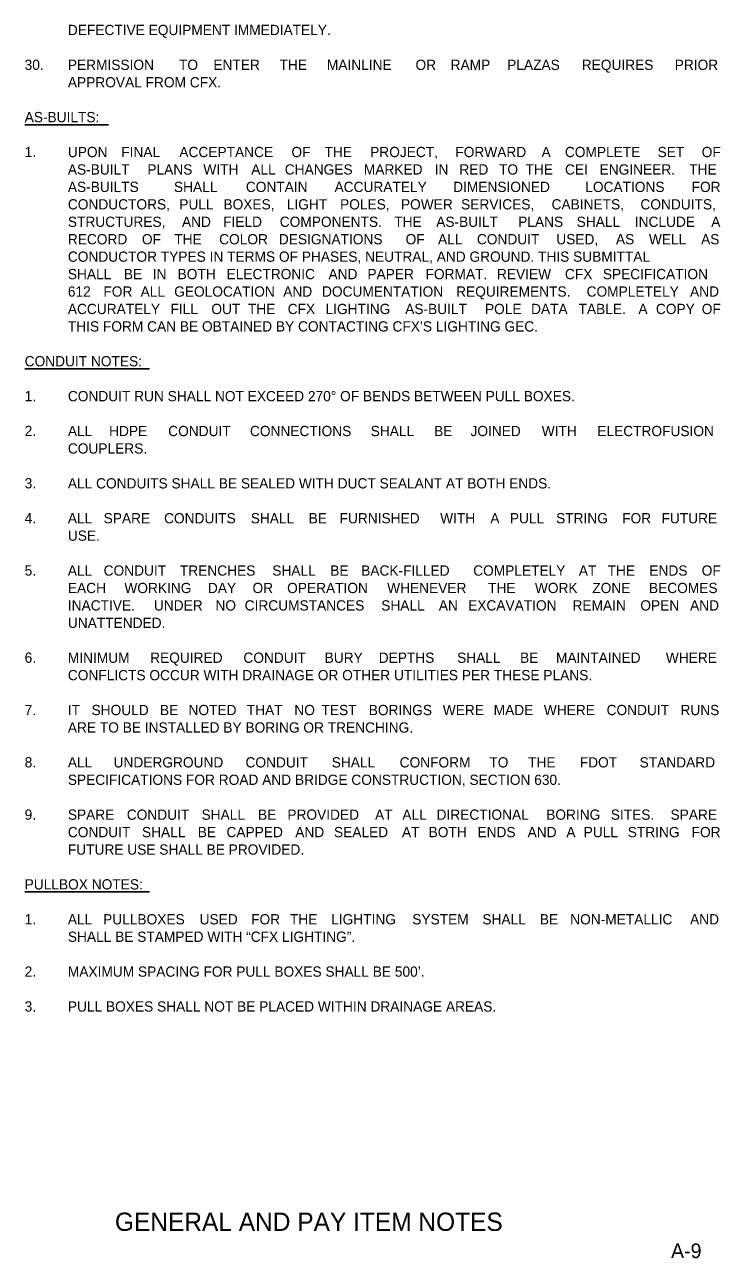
# Model space of a CAD drawing. Extents: x -55 to 2471539, y -90 to 3608906.
# Drawn here: x 1052 to 1526, y -65 to 777 of the extents above; entities that cross this region are included whole.
import ezdxf

# ---------------------------------------------------------------- set-up
doc = ezdxf.new("R2010")
doc.units = 0
for name, color, linetype in [('SheetLines_dp', 7, 'Continuous'), ('TextMisc', 7, 'Continuous'), ('XSCell', 7, 'Continuous')]:
    doc.layers.add(name, color=color, linetype=linetype)

msp = doc.modelspace()

# ---------------------------------------------------------------- linework, layer by layer
at = {"layer": 'XSCell'}
for p, q in [((1051.51, 708.96), (1108.73, 708.96)), ((1051.51, 542.36), (1136.69, 542.36)), ((1051.51, 185.36), (1136.73, 185.36))]:
    msp.add_line(p, q, dxfattribs=at)

# ---------------------------------------------------------------- texts
at = {"layer": 'SheetLines_dp'}
msp.add_text('A-9', height=10, dxfattribs=at).set_placement((1492.64, -64.49))
at = {"layer": 'TextMisc'}
msp.add_text('GENERAL AND PAY ITEM NOTES ', height=12.5, dxfattribs=at).set_placement((1113.09, -45.92))
at = {"layer": 'XSCell'}
for s, p in [('DEFECTIVE EQUIPMENT IMMEDIATELY.', (1080.99, 770.14)), ('30.', (1051.5, 746.38)), ('PERMISSION ', (1080.99, 746.34)), ('TO ', (1156.84, 746.34)), ('ENTER ', (1180.3, 746.34)), ('THE ', (1225.48, 746.34)), ('MAINLINE ', (1257.78, 746.34)), ('OR ', (1318.26, 746.34)), ('RAMP ', (1342.22, 746.34)), ('PLAZAS ', (1380.82, 746.34)), ('REQUIRES ', (1431.73, 746.34)), ('PRIOR ', (1495.16, 746.34)), ('APPROVAL FROM CFX.', (1080.99, 734.44)), ('AS-BUILTS:', (1051.5, 710.68)), ('1.', (1051.5, 686.88)), ('UPON ', (1080.99, 686.84)), ('FINAL ', (1117.41, 686.84)), ('ACCEPTANCE ', (1157.09, 686.84)), ('OF ', (1233.58, 686.84)), ('THE ', (1256.2, 686.84)), ('PROJECT, ', (1287.31, 686.84)), ('FORWARD ', (1345.45, 686.84)), ('A ', (1404.28, 686.84)), ('COMPLETE ', (1420.22, 686.84)), ('SET ', (1483.47, 686.84)), ('OF ', (1513.59, 686.84)), ('AS-BUILT ', (1080.99, 674.94)), ('PLANS ', (1135.26, 674.94)), ('WITH ', (1173.46, 674.94)), ('ALL ', (1206.16, 674.94)), ('CHANGES ', (1229.03, 674.94)), ('MARKED ', (1283, 674.94)), ('IN ', (1331.35, 674.94)), ('RED ', (1348.18, 674.94)), ('TO ', (1375.25, 674.94)), ('THE ', (1393.35, 674.94)), ('CEI ', (1420.3, 674.94)), ('ENGINEER. ', (1443.89, 674.94)), ('THE ', (1505.1, 674.94)), ('AS-BUILTS ', (1080.99, 663.04)), ('SHALL ', (1153.39, 663.04)), ('CONTAIN ', (1202.46, 663.04)), ('ACCURATELY ', (1263, 663.04)), ('DIMENSIONED ', (1343.94, 663.04)), ('LOCATIONS ', (1434.11, 663.04)), ('FOR ', (1506.71, 663.04)), ('CONDUCTORS, ', (1080.99, 651.14)), ('PULL ', (1157.04, 651.14)), ('BOXES, ', (1187.18, 651.14)), ('LIGHT ', (1230.39, 651.14)), ('POLES, ', (1266.78, 651.14)), ('POWER ', (1308.31, 651.14)), ('SERVICES, ', (1349.37, 651.14)), ('CABINETS, ', (1411.13, 651.14)), ('CONDUITS, ', (1471.76, 651.14)), ('STRUCTURES, ', (1080.99, 639.24)), ('AND ', (1158.87, 639.24)), ('FIELD ', (1186.95, 639.24)), ('COMPONENTS. ', (1225.61, 639.24)), ('THE ', (1303.77, 639.24)), ('AS-BUILT ', (1332.39, 639.24)), ('PLANS ', (1388.33, 639.24)), ('SHALL ', (1428.22, 639.24)), ('INCLUDE ', (1467.92, 639.24)), ('A ', (1520.06, 639.24)), ('RECORD ', (1080.99, 627.34)), ('OF ', (1131.52, 627.34)), ('THE ', (1153.64, 627.34)), ('COLOR ', (1184.25, 627.34)), ('DESIGNATIONS ', (1225, 627.34)), ('OF ', (1311.51, 627.34)), ('ALL ', (1333.62, 627.34)), ('CONDUIT ', (1360.16, 627.34)), ('USED, ', (1414.35, 627.34)), ('AS ', (1455.05, 627.34)), ('WELL ', (1477.57, 627.34)), ('AS ', (1513.18, 627.34)), ('CONDUCTOR TYPES IN TERMS OF PHASES, NEUTRAL, AND GROUND. THIS SUBMITTAL ', (1080.99, 615.44)), ('SHALL ', (1080.99, 603.54)), ('BE ', (1119.17, 603.54)), ('IN ', (1138.91, 603.54)), ('BOTH ', (1155.9, 603.54)), ('ELECTRONIC ', (1189.32, 603.54)), ('AND ', (1258.87, 603.54)), ('PAPER ', (1285.43, 603.54)), ('FORMAT. ', (1325.11, 603.54)), ('REVIEW ', (1373.87, 603.54)), ('CFX ', (1420.25, 603.54)), ('SPECIFICATION ', (1446.08, 603.54)), ('612 ', (1080.99, 591.64)), ('FOR ', (1105.26, 591.64)), ('ALL ', (1130.64, 591.64)), ('GEOLOCATION ', (1153.56, 591.64)), ('AND ', (1227.99, 591.64)), ('DOCUMENTATION ', (1254.44, 591.64)), ('REQUIREMENTS. ', (1345.98, 591.64)), ('COMPLETELY ', (1435.03, 591.64)), ('AND ', (1505.64, 591.64)), ('ACCURATELY ', (1080.99, 579.74)), ('FILL ', (1151.05, 579.74)), ('OUT ', (1178.93, 579.74)), ('THE ', (1203.92, 579.74)), ('CFX ', (1231.04, 579.74)), ('LIGHTING ', (1256.88, 579.74)), ('AS-BUILT ', (1311.22, 579.74)), ('POLE ', (1365.65, 579.74)), ('DATA ', (1397.11, 579.74)), ('TABLE. ', (1429.54, 579.74)), ('A ', (1470.38, 579.74)), ('COPY ', (1482.33, 579.74)), ('OF ', (1513.59, 579.74)), ('THIS FORM CAN BE OBTAINED BY CONTACTING CFX’S LIGHTING GEC.', (1080.99, 567.84)), ('CONDUIT NOTES:', (1051.5, 544.08)), ('1.', (1051.5, 520.28)), ('CONDUIT RUN SHALL NOT EXCEED 270° OF BENDS BETWEEN PULL BOXES.', (1080.99, 520.24)), ('2.', (1051.5, 496.48)), ('ALL ', (1080.99, 496.44)), ('HDPE ', (1109.12, 496.44)), ('CONDUIT ', (1149.48, 496.44)), ('CONNECTIONS ', (1205.26, 496.44)), ('SHALL ', (1287.67, 496.44)), ('BE ', (1330.94, 496.44)), ('JOINED ', (1355.77, 496.44)), ('WITH ', (1404.4, 496.44)), ('ELECTROFUSION ', (1442.34, 496.44)), ('COUPLERS.', (1080.99, 484.54)), ('3.', (1051.5, 460.78)), ('ALL CONDUITS SHALL BE SEALED WITH DUCT SEALANT AT BOTH ENDS.', (1080.99, 460.74)), ('4.', (1051.5, 436.98)), ('ALL ', (1080.99, 436.94)), ('SPARE ', (1105.4, 436.94)), ('CONDUITS ', (1146.66, 436.94)), ('SHALL ', (1205.81, 436.94)), ('BE ', (1245.36, 436.94)), ('FURNISHED ', (1266.47, 436.94)), ('WITH ', (1335.1, 436.94)), ('A ', (1369.33, 436.94)), ('PULL ', (1382.64, 436.94)), ('STRING ', (1414.2, 436.94)), ('FOR ', (1459.3, 436.94)), ('FUTURE ', (1486.16, 436.94)), ('USE.', (1080.99, 425.04)), ('5.', (1051.5, 401.28)), ('ALL ', (1080.99, 401.24)), ('CONDUIT ', (1105.4, 401.24)), ('TRENCHES ', (1157.46, 401.24)), ('SHALL ', (1220.52, 401.24)), ('BE ', (1260.08, 401.24)), ('BACK-FILLED ', (1281.18, 401.24)), ('COMPLETELY ', (1357.62, 401.24)), ('AT ', (1429.7, 401.24)), ('THE ', (1449.39, 401.24)), ('ENDS ', (1477.86, 401.24)), ('OF ', (1513.59, 401.24)), ('EACH ', (1080.99, 389.34)), ('WORKING ', (1119.56, 389.34)), ('DAY ', (1176.58, 389.34)), ('OR ', (1207.01, 389.34)), ('OPERATION ', (1230.64, 389.34)), ('WHENEVER ', (1298.91, 389.34)), ('THE ', (1367.77, 389.34)), ('WORK ', (1399.74, 389.34)), ('ZONE ', (1438.89, 389.34)), ('BECOMES ', (1477.59, 389.34)), ('INACTIVE. ', (1080.99, 377.44)), ('UNDER ', (1139.72, 377.44)), ('NO ', (1181.71, 377.44)), ('CIRCUMSTANCES ', (1201.67, 377.44)), ('SHALL ', (1294.86, 377.44)), ('AN ', (1334.17, 377.44)), ('EXCAVATION ', (1354.17, 377.44)), ('REMAIN ', (1425.41, 377.44)), ('OPEN ', (1471.68, 377.44)), ('AND ', (1505.64, 377.44)), ('UNATTENDED. ', (1080.99, 365.54)), ('6.', (1051.5, 341.78)), ('MINIMUM ', (1080.99, 341.74)), ('REQUIRED ', (1137.17, 341.74)), ('CONDUIT ', (1200.79, 341.74)), ('BURY ', (1256.25, 341.74)), ('DEPTHS ', (1293.15, 341.74)), ('SHALL ', (1346.65, 341.74)), ('BE ', (1389.61, 341.74)), ('MAINTAINED ', (1414.12, 341.74)), ('WHERE ', (1489.11, 341.74)), ('CONFLICTS OCCUR WITH DRAINAGE OR OTHER UTILITIES PER THESE PLANS.', (1080.99, 329.84)), ('7.', (1051.5, 306.08)), ('IT ', (1080.99, 306.04)), ('SHOULD ', (1097.15, 306.04)), ('BE ', (1143.86, 306.04)), ('NOTED ', (1163.32, 306.04)), ('THAT ', (1203.08, 306.04)), ('NO ', (1235.56, 306.04)), ('TEST ', (1254.12, 306.04)), ('BORINGS ', (1286.34, 306.04)), ('WERE ', (1336.87, 306.04)), ('MADE ', (1371.62, 306.04)), ('WHERE ', (1405.84, 306.04)), ('CONDUIT ', (1448.66, 306.04)), ('RUNS ', (1499.08, 306.04)), ('ARE TO BE INSTALLED BY BORING OR TRENCHING. ', (1080.99, 294.14)), ('8.', (1051.5, 270.38)), ('ALL ', (1080.99, 270.34)), ('UNDERGROUND ', (1112.19, 270.34)), ('CONDUIT ', (1202.21, 270.34)), ('SHALL ', (1261.07, 270.34)), ('CONFORM ', (1307.42, 270.34)), ('TO ', (1368.66, 270.34)), ('THE ', (1395.1, 270.34)), ('FDOT ', (1430.37, 270.34)), ('STANDARD ', (1471.21, 270.34)), ('SPECIFICATIONS FOR ROAD AND BRIDGE CONSTRUCTION, SECTION 630.', (1080.99, 258.44)), ('9.', (1051.5, 234.68)), ('SPARE ', (1080.99, 234.64)), ('CONDUIT ', (1121.21, 234.64)), ('SHALL ', (1172.23, 234.64)), ('BE ', (1210.74, 234.64)), ('PROVIDED ', (1230.81, 234.64)), ('AT ', (1290.64, 234.64)), ('ALL ', (1309.28, 234.64)), ('DIRECTIONAL ', (1332.64, 234.64)), ('BORING ', (1407.45, 234.64)), ('SITES. ', (1451.51, 234.64)), ('SPARE ', (1492.31, 234.64)), ('CONDUIT ', (1080.99, 222.74)), ('SHALL ', (1131.57, 222.74)), ('BE ', (1169.63, 222.74)), ('CAPPED ', (1189.25, 222.74)), ('AND ', (1236.18, 222.74)), ('SEALED ', (1262.62, 222.74)), ('AT ', (1309.03, 222.74)), ('BOTH ', (1327.22, 222.74)), ('ENDS ', (1360.52, 222.74)), ('AND ', (1394.76, 222.74)), ('A ', (1421.21, 222.74)), ('PULL ', (1433.03, 222.74)), ('STRING ', (1463.1, 222.74)), ('FOR ', (1506.71, 222.74)), ('FUTURE USE SHALL BE PROVIDED.', (1080.99, 210.84)), ('PULLBOX NOTES:', (1051.5, 187.08)), ('1.', (1051.5, 163.28)), ('ALL ', (1080.99, 163.24)), ('PULLBOXES ', (1105.04, 163.24)), ('USED ', (1170.93, 163.24)), ('FOR ', (1206.08, 163.24)), ('THE ', (1232.58, 163.24)), ('LIGHTING ', (1260.7, 163.24)), ('SYSTEM ', (1316.04, 163.24)), ('SHALL ', (1363.9, 163.24)), ('BE ', (1403.1, 163.24)), ('NON-METALLIC ', (1423.85, 163.24)), ('AND ', (1505.64, 163.24)), ('SHALL BE STAMPED WITH “CFX LIGHTING”.', (1080.99, 151.34)), ('2. ', (1051.5, 127.58)), ('MAXIMUM SPACING FOR PULL BOXES SHALL BE 500’. ', (1080.99, 127.54)), ('3.', (1051.5, 103.78)), ('PULL BOXES SHALL NOT BE PLACED WITHIN DRAINAGE AREAS.', (1080.99, 103.74))]:
    msp.add_text(s, height=7, dxfattribs=at).set_placement(p)

doc.saveas('drawing.dxf')
